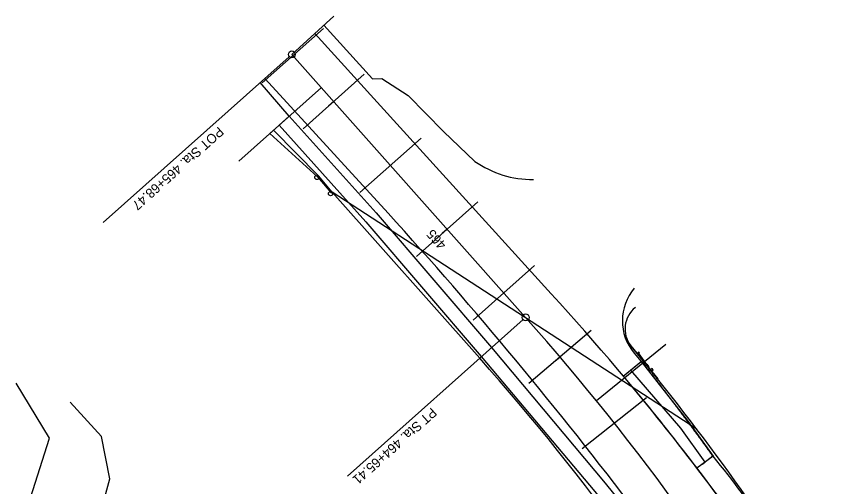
# Model space of a CAD drawing. Extents: x 2355002 to 2355569, y 708374 to 709566.
# Drawn here: x 2355092.3 to 2355330.7, y 709427.8 to 709565.5 of the extents above; entities that cross this region are included whole.
import ezdxf

# ---------------------------------------------------------------- set-up
doc = ezdxf.new("R2010")
doc.units = 0
for name, color, linetype in [('BD_X_Building', 7, 'Continuous'), ('HY_X_Water_Edge', 7, 'Continuous'), ('PM_X_CL_Double_Solid', 7, 'Continuous'), ('PM_X_Edge_Line', 7, 'Continuous'), ('PV_X_EOP', 7, 'Continuous'), ('RD_X_GR_Lt', 7, 'Continuous'), ('RD_X_Wall', 7, 'Continuous'), ('SH_Text', 7, 'Continuous'), ('SN_X_Private', 7, 'Continuous'), ('UT_X_Water_Cells', 7, 'Continuous')]:
    doc.layers.add(name, color=color, linetype=linetype)

msp = doc.modelspace()

# ---------------------------------------------------------------- linework, layer by layer
at = {"layer": 'BD_X_Building'}
for p, q in [((2355164.41, 709546.02), (2355182.35, 709561.97)), ((2355194.31, 709548.52), (2355176.38, 709532.57)), ((2355157.51, 709523.08), (2355181.72, 709544.62)), ((2355192.99, 709513.89), (2355210.93, 709529.84)), ((2355291.72, 709444.63), (2355184.89, 709513.98)), ((2355209.61, 709495.21), (2355227.54, 709511.16)), ((2355226.23, 709476.53), (2355244.16, 709492.49)), ((2355260.82, 709473.5), (2355242.55, 709457.94)), ((2355282.67, 709469.36), (2355262.38, 709452.87)), ((2355258.16, 709438.95), (2355276.96, 709453.87))]:
    msp.add_line(p, q, dxfattribs=at)
at = {"layer": 'HY_X_Water_Edge'}
for points in [[(2355252.5, 709166.15), (2355231.06, 709173.66), (2355214.15, 709182.36), (2355203.37, 709187.9), (2355192.59, 709193.45), (2355183.53, 709205.69), (2355174.46, 709217.93), (2355164.58, 709222.52), (2355164.39, 709236.17), (2355153.02, 709259.61), (2355143.04, 709280.19), (2355127.94, 709298.41), (2355115.77, 709313.1), (2355105.23, 709336.59), (2355094.69, 709360.09), (2355095.83, 709378.33), (2355096.98, 709396.58), (2355097.73, 709408.64), (2355093.09, 709413.75), (2355102.05, 709442.02), (2355092.33, 709458.07)], [(2355243.42, 709195.53), (2355235.94, 709194.52), (2355230.17, 709190.58), (2355225.57, 709193.22), (2355215.6, 709195.99), (2355205.62, 709198.76), (2355197.48, 709205.94), (2355189.34, 709213.12), (2355179.68, 709238.25), (2355173.07, 709264.93), (2355160.61, 709293.02), (2355152.36, 709311.63), (2355137.42, 709323.36), (2355122.48, 709335.09), (2355113.93, 709360.3), (2355113.17, 709374.34), (2355109.09, 709386.01), (2355109.6, 709398.21), (2355114.81, 709412.22), (2355119.75, 709430.04), (2355117.27, 709442.45), (2355108.11, 709452.56)]]:
    msp.add_lwpolyline(points, dxfattribs=at)
at = {"layer": 'PM_X_CL_Double_Solid'}
msp.add_line((2355241.57, 709477.34), (2355173.07, 709554.35), dxfattribs=at)
msp.add_arc((2354704.75, 708999.81), 718.47, 29.69206, 41.65532, dxfattribs=at)
at = {"layer": 'PM_X_Edge_Line'}
for p, q in [((2355249.07, 709484.23), (2355179.81, 709560.47)), ((2355201.26, 709507.84), (2355165.22, 709547.15))]:
    msp.add_line(p, q, dxfattribs=at)
for centre, radius, start, end in [((2354267.28, 708657.32), 1263.21, 37.15047, 42.32198), ((2354710.32, 708989.77), 731.26, 33.34928, 42.54487)]:
    msp.add_arc(centre, radius, start, end, dxfattribs=at)
at = {"layer": 'PV_X_EOP'}
for p, q in [((2355172.31, 709536.25), (2355163.79, 709546.09)), ((2355217.54, 709531.77), (2355226.73, 709523.03)), ((2355273.39, 709466.85), (2355275.45, 709464.45)), ((2355270.19, 709460.17), (2355275.49, 709464.48)), ((2355272.35, 709461.92), (2355275.45, 709464.45)), ((2355296.52, 709436.73), (2355291.77, 709433.22)), ((2355296.43, 709436.66), (2355293.39, 709434.41)), ((2355293.39, 709434.41), (2355294.12, 709434.95))]:
    msp.add_line(p, q, dxfattribs=at)
for points in [[(2355182.48, 709562.9), (2355196.74, 709547.17), (2355199.45, 709547.26), (2355207.17, 709542.31), (2355217.54, 709531.77)], [(2355172.31, 709536.25), (2355197.77, 709507.92), (2355231.62, 709468.51), (2355264.91, 709428.85), (2355272.57, 709419.22)], [(2355272.35, 709461.92), (2355286.91, 709444.94), (2355294.09, 709434.98)]]:
    msp.add_lwpolyline(points, dxfattribs=at)
for centre, radius, start, end in [((2355243.33, 709546.5), 28.75, 234.7247, 271.0182), ((2355284.67, 709476.38), 14.76, 139.6703, 220.1675), ((2354710.32, 708989.77), 731.26, 37.33096, 40.03636), ((2354950.62, 709158.75), 443.76, 31.5343, 38.7868), ((2354710.32, 708989.77), 731.26, 33.34928, 37.33065)]:
    msp.add_arc(centre, radius, start, end, dxfattribs=at)
msp.add_open_spline([(2355275.49, 709464.48), (2355275.85, 709464.02), (2355276.57, 709463.11), (2355277.65, 709461.74), (2355278.72, 709460.37), (2355279.79, 709458.99), (2355280.85, 709457.62), (2355281.91, 709456.24), (2355282.97, 709454.86), (2355284.03, 709453.47), (2355285.08, 709452.08), (2355286.13, 709450.69), (2355287.17, 709449.3), (2355288.22, 709447.91), (2355289.26, 709446.51), (2355290.29, 709445.11), (2355291.32, 709443.71), (2355292.35, 709442.3), (2355293.38, 709440.9), (2355294.4, 709439.49), (2355295.42, 709438.08), (2355296.09, 709437.13), (2355296.43, 709436.66)], degree=3, dxfattribs=at)
at = {"layer": 'RD_X_GR_Lt'}
for p, q in [((2355167.68, 709532.12), (2355166.61, 709531.2)), ((2355180.87, 709518.76), (2355167.68, 709532.12)), ((2355166.61, 709531.2), (2355180.63, 709518.54)), ((2355180.63, 709518.54), (2355184.63, 709513.77)), ((2355184.89, 709513.98), (2355180.87, 709518.76)), ((2355184.63, 709513.77), (2355184.89, 709513.98)), ((2355184.63, 709513.77), (2355184.89, 709513.98)), ((2355228.12, 709465.38), (2355184.89, 709513.98))]:
    msp.add_line(p, q, dxfattribs=at)
for centre in [(2355180.41, 709518.34), (2355184.41, 709513.58)]:
    msp.add_circle(centre, 0.624, dxfattribs=at)
for centre, radius, start, end in [((2355278.7, 709473.97), 8, 128.3691, 217.8938), ((2354704.75, 708999.81), 736.47, 31.79992, 39.57967), ((2354704.75, 708999.81), 700.47, 30.10541, 41.65532)]:
    msp.add_arc(centre, radius, start, end, dxfattribs=at)
at = {"layer": 'RD_X_Wall'}
for p, q in [((2355173.07, 709554.35), (2355185.36, 709565.51)), ((2355172.32, 709553.68), (2355117.74, 709505.13)), ((2355241.57, 709477.34), (2355173.07, 709554.35)), ((2355185.34, 709540.55), (2355183.85, 709539.22)), ((2355218.58, 709503.19), (2355217.08, 709501.86)), ((2355251.68, 709465.72), (2355250.16, 709464.42))]:
    msp.add_line(p, q, dxfattribs=at)
for centre in [(2355173.07, 709554.35), (2355241.57, 709477.34)]:
    msp.add_circle(centre, 1, dxfattribs=at)
msp.add_arc((2354704.75, 708999.81), 718.47, 29.69206, 41.65532, dxfattribs=at)
at = {"layer": 'SH_Text'}
msp.add_line((2355240.82, 709476.68), (2355189.34, 709430.88), dxfattribs=at)
at = {"layer": 'SN_X_Private'}
for p, q in [((2355272.38, 709469.06), (2355280.27, 709459.35)), ((2355274.74, 709466.65), (2355276.99, 709463.59)), ((2355276.89, 709463.51), (2355277.08, 709463.67)), ((2355277.08, 709463.67), (2355277.71, 709462.89)), ((2355277.52, 709462.73), (2355277.71, 709462.89))]:
    msp.add_line(p, q, dxfattribs=at)
for points in [[(2355274.21, 709466.81), (2355274.5, 709466.45), (2355274.98, 709466.85), (2355274.7, 709467.2)], [(2355278.15, 709461.96), (2355278.44, 709461.6), (2355278.93, 709462), (2355278.64, 709462.35)]]:
    msp.add_lwpolyline(points, close=True, dxfattribs=at)
at = {"layer": 'UT_X_Water_Cells'}
msp.add_line((2355169.32, 709533.59), (2355172.31, 709536.25), dxfattribs=at)
for points in [[(2355169.32, 709533.59), (2355194.77, 709505.28), (2355228.57, 709465.92), (2355261.82, 709426.32), (2355269.44, 709416.73)], [(2355275.45, 709464.45), (2355289.16, 709446.85), (2355296.52, 709436.73)]]:
    msp.add_lwpolyline(points, dxfattribs=at)

# ---------------------------------------------------------------- texts
at = {"layer": 'BD_X_Building'}
msp.add_text('X', height=0.14, rotation=25.0808, dxfattribs=at).set_placement((2355168.24, 709532.57))
msp.add_text('X', height=0.14, rotation=25.0808, dxfattribs=at).set_placement((2355168.24, 709532.57))
at = {"layer": 'RD_X_Wall'}
for s, rotation, p in [('POT Sta. 465+68.47', 221.6553, (2355151.58, 709533.36)), ('465', 131.6553, (2355218.53, 709498.73))]:
    msp.add_text(s, height=2.8, rotation=rotation, dxfattribs=at).set_placement(p)
at = {"layer": 'SH_Text'}
msp.add_text('PT Sta. 464+65.41', height=2.8, rotation=221.6553, dxfattribs=at).set_placement((2355214, 709451.1))

doc.saveas('drawing.dxf')
